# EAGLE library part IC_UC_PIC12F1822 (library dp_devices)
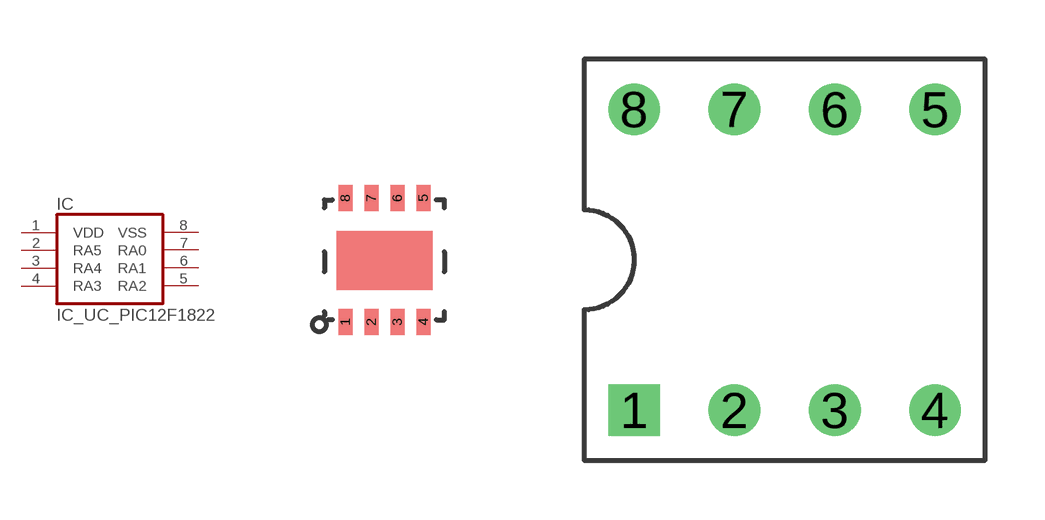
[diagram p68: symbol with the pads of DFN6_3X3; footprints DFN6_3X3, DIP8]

Designator prefix IC

## IC_UC_PIC12F1822DFN6_3X3  [DFN6_3X3]
1  VDD  pwr
2  RA5
3  RA4
4  RA3
5  RA2
6  RA1
7  RA0
8  VSS  pwr

## IC_UC_PIC12F1822DIP8  [DIP8]
Pads as for DFN6_3X3

## Footprint DFN6_3X3 (pad centres in mm)
smd 0.35 x 0.65: 1 -0.975,-1.55; 2 -0.325,-1.55; 3 0.325,-1.55; 4 0.975,-1.55; 5 0.975,1.55; 6 0.325,1.55; 7 -0.325,1.55; 8 -0.975,1.55

## Footprint DIP8 (pad centres in mm)
drill 0.8 square: 1 -3.81,-3.81
drill 0.8 round: 2 -1.27,-3.81; 3 1.27,-3.81; 4 3.81,-3.81; 5 3.81,3.81; 6 1.27,3.81; 7 -1.27,3.81; 8 -3.81,3.81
